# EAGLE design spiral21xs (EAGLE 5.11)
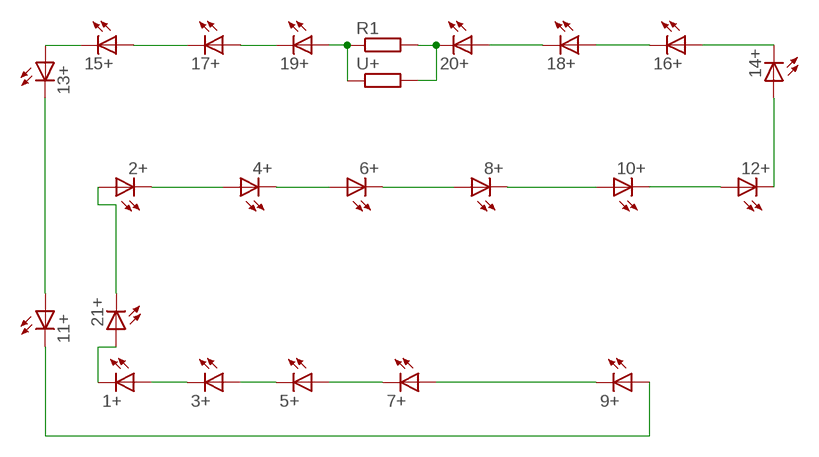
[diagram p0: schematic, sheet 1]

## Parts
1+  LEDSMD1210  [1210]
2+  LEDSMD1210  [1210]
3+  LEDSMD1210  [1210]
4+  LEDSMD1210  [1210]
5+  LEDSMD1210  [1210]
6+  LEDSMD1210  [1210]
7+  LEDSMD1210  [1210]
8+  LEDSMD1210  [1210]
9+  LEDSMD1210  [1210]
10+  LEDSMD1210  [1210]
11+  LEDSMD1210  [1210]
12+  LEDSMD1210  [1210]
13+  LEDSMD1210  [1210]
14+  LEDSMD1210  [1210]
15+  LEDSMD1210  [1210]
16+  LEDSMD1210  [1210]
17+  LEDSMD1210  [1210]
18+  LEDSMD1210  [1210]
19+  LEDSMD1210  [1210]
20+  LEDSMD1210  [1210]
21+  LEDSMD1210  [1210]
R1  R-EU_R1206  [R1206]
U+  R-EU_0204/2V  [0204V]

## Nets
MINUS: 20+.C R1.2 U+.2
N1-3: 1+.A 3+.C
N2-4: 2+.C 4+.A
N2-21: 2+.A 21+.C
N3-5: 3+.A 5+.C
N4-6: 4+.C 6+.A
N5-7: 5+.A 7+.C
N6-8: 6+.C 8+.A
N7-9: 7+.A 9+.C
N8-10: 8+.C 10+.A
N9-11: 9+.A 11+.C
N10-12: 10+.C 12+.A
N11-13: 11+.A 13+.C
N12-14: 12+.C 14+.A
N13-15: 13+.A 15+.C
N14-16: 14+.C 16+.A
N15-17: 15+.A 17+.C
N16-18: 16+.C 18+.A
N17-19: 17+.A 19+.C
N18-20: 18+.C 20+.A
N21-1: 1+.C 21+.A
PLUS: 19+.A R1.1 U+.1

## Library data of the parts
1+ 2+ 3+ 4+ 5+ 6+ 7+ 8+ 9+ 10+ 11+ 12+ 13+ 14+ 15+ 16+ 17+ 18+ 19+ 20+ 21+ = led(2):LED: LED
R1 U+ = rcl-2:R-EU_: RESISTOR, European symbol

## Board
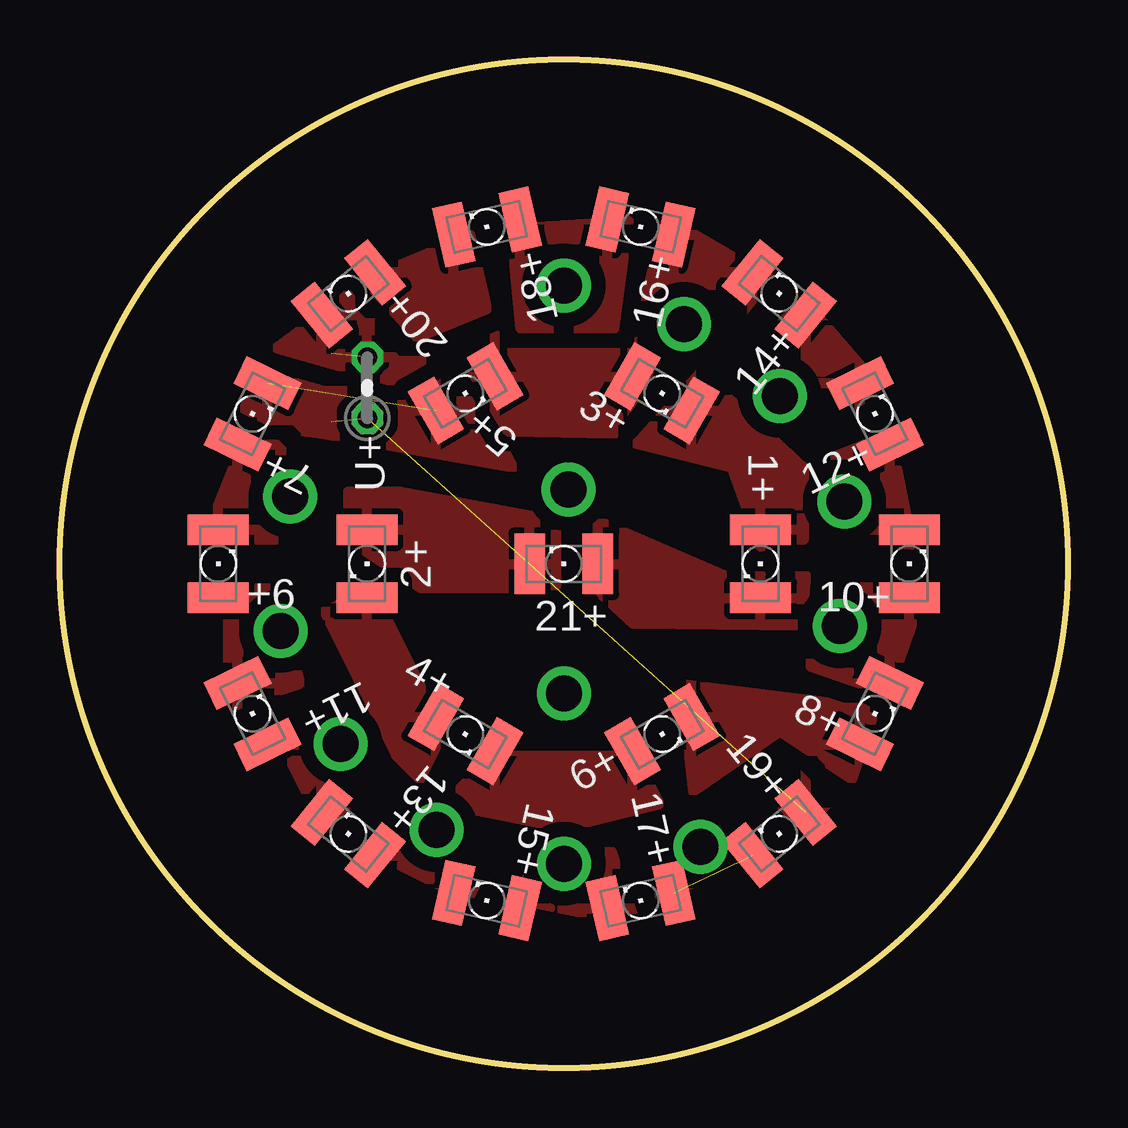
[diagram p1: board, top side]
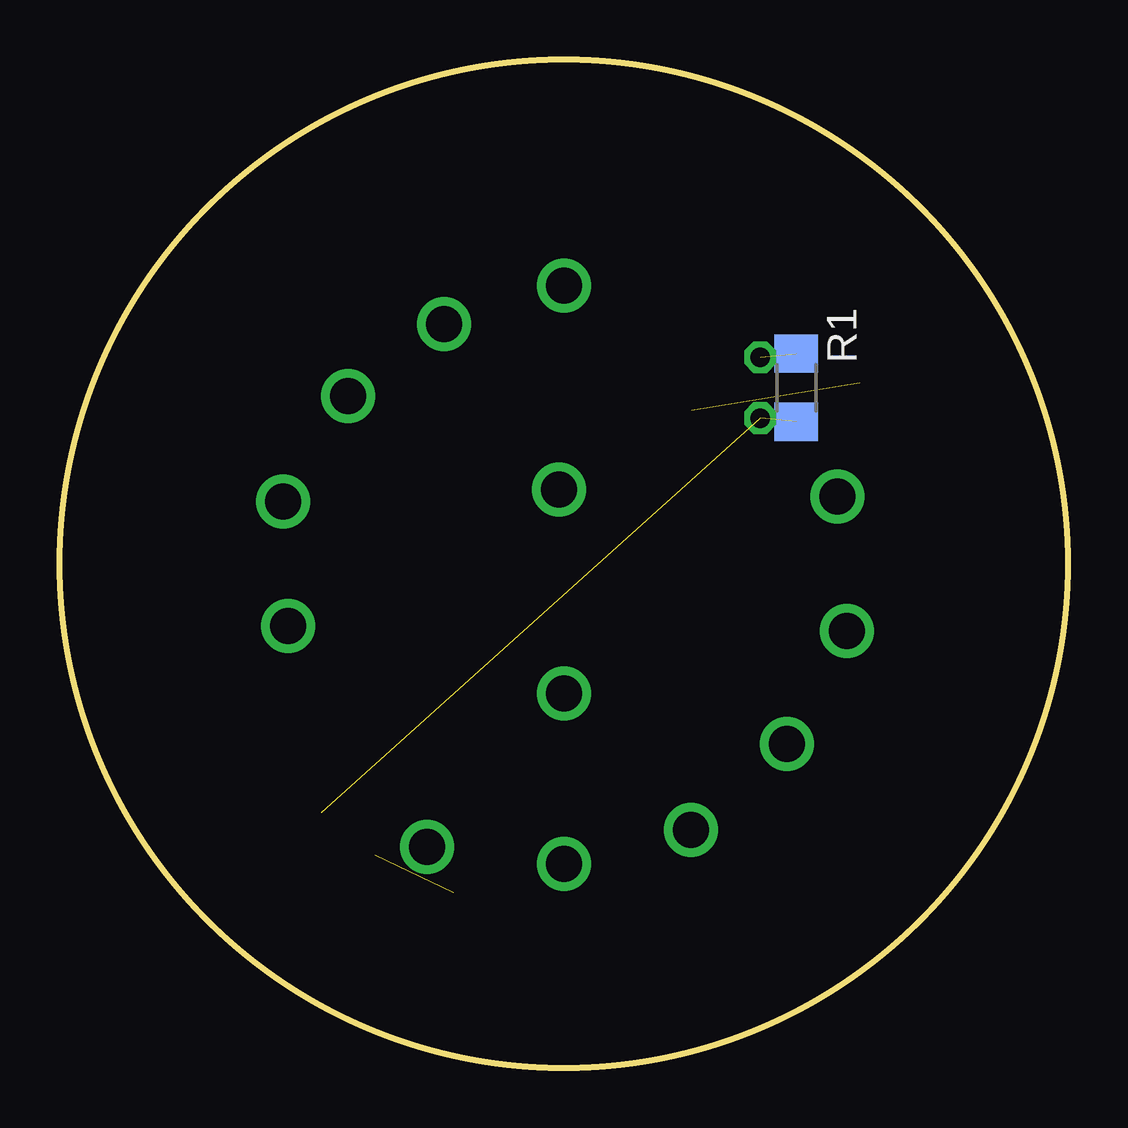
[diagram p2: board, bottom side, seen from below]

Size 42 x 42 mm. Coordinates in mm from the lower left corner, seen from the top.
Outline: circle at 21,21 radius 21
Copper layers (1*16): Top 0.035mm / dielectric 1.5mm / Bottom 0.035mm
Design rules "default": minimum track width 10mil, minimum drill 24mil, track to track 8mil, track to pad 8mil, pad to pad 8mil, via to via 8mil, smd to smd 8mil, copper to edge 40mil, drill to drill 8mil, minimum pad ring 10mil, minimum via ring 8mil, stop-mask expansion 4mil, vias tented up to drill 0mil, thermal gap 10mil

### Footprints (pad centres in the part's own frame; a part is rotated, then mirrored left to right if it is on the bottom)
1210 = smd 1.27 x 2.54: A -1.422,0; C 1.422,0
R1206 = smd 1.6 x 1.803: 1 -1.422,0; 2 1.422,0
0204V = drill 0.813 octagon: 1 -1.27,0; 2 1.27,0

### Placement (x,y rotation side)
1+  29.2,21 270 top
2+  12.8,21 270 top
3+  25.1,28.1 330 top
4+  16.9,13.9 330 top
5+  16.9,28.1 30 top
6+  25.1,13.9 30 top
7+  8.03,27.25 64 top
8+  33.97,14.75 64 top
9+  6.6,21 90 top
10+  35.4,21 90 top
11+  8.03,14.75 116 top
12+  33.97,27.25 116 top
13+  12.02,9.74 141 top
14+  29.98,32.26 141 top
15+  17.8,6.96 167 top
16+  24.2,35.04 167 top
17+  24.2,6.96 193 top
18+  17.8,35.04 193 top
19+  29.98,9.74 219 top
20+  12.02,32.26 219 top
21+  21,21 180 top
R1  11.31,28.34 90 bottom
U+  12.81,28.34 90 top

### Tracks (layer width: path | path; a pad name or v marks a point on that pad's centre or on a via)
HOL1  (via drill 1.5)
  other vias: 21,15.6
MINUS  (1 unrouted)
  pour Top (isolate 0.61, rank 3): 9,30 16,28 13,33
N1-3
  pour Top (isolate 0.61): 24,26 26.7,29 31,25 31,22 29.2,21.7 28,25
N2-4
  pour Top (isolate 0.61, rank 2): 13,20 11,19 14,13 15,12 16,14
N2-21
  pour Top (isolate 0.61, rank 2): 12,24 12,22 15,20 20,20 20.7,20.1 20.7,22.8 14.2,24
N3-5
  pour Top (isolate 0.61, rank 3): 17.2,29 17.2,30.7 25.2,30.2 23.1,26.4 18.7,26.5
N4-6
  pour Top (isolate 0.61, rank 2): 18,13 17,12 16,11 21,10 25,11 24,13 20,13
N5-7  (1 unrouted)
  pour Top (isolate 0.61, rank 4): 8,29 16.8,28.9 18.9,25 10.9,26.4 7.6,26.8
N6-8
  pour Top (isolate 0.61, rank 3): 26,15 26,16 34,15 33,12 30,14 26.4,11.5
N7-9
  pour Top (isolate 0.61, rank 2): 8,27 10,25 9,22 6,22
N8-10
  pour Top (isolate 0.61, rank 2): 31,20 36.1,20.1 34.5,15.6 31.3,16.7
N9-11
  pour Top (isolate 0.61, rank 2): 7,20 9,20 10,16 7,15
N10-12
  pour Top (isolate 0.61, rank 2): 31,25 34.6,26.4 35.5,21.8 31.1,21.7
N11-13
  pour Top (isolate 0.61, rank 2): 9,14 11,15 13,12 11,10
N12-14
  pour Top (isolate 0.61, rank 2): 31,32 34.2,28.3 31.2,26.5 28.3,29.3
N13-15
  pour Top (isolate 0.61, rank 2): 13,9 14,11 18,9 17,7
N14-16
  pour Top (isolate 0.61, rank 2): 26,35 29.6,32.9 27.4,30.2 24.3,31.6 25.2,35.2
N15-17
  pour Top (isolate 0.61, rank 2): 19,7 20,9 23,9 24,6
N16-18
  pour Top (isolate 0.61, rank 2): 19,35 23.7,35.3 23.1,30.8 19.2,30.8 18.8,35
N17-19  (1 unrouted)
  pour Top (isolate 0.61, rank 2): 25,7 25,9 28,10 29,9
N18-20
  pour Top (isolate 0.61, rank 2): 13,33 17.1,34.7 17.8,31.6 14.9,30.4 12.9,32.6
N21-1
  pour Top (isolate 0.61): 22,22 22,23 27.8,20.5 31.1,20.5 30.9,18.4 23.9,18.5 22.6,19.7
N$1  (via drill 1.5)
  other vias: 26,31
N$2  (via drill 1.5)
  other vias: 30,28
N$3  (via drill 1.5)
  other vias: 32.7,23.6
N$4  (via drill 1.5)
  other vias: 32.5,18.4
N$5  (via drill 1.5)
  other vias: 26.7,9.2
N$6  (via drill 1.5)
  other vias: 21,8.5
N$7  (via drill 1.5)
  other vias: 15.7,9.9
N$8  (via drill 1.5)
  other vias: 11.7,13.5
N$9  (via drill 1.5)
  other vias: 9.2,18.2
N$10  (via drill 1.5)
  other vias: 9.6,23.8
N$11  (via drill 1.5)
  other vias: 21,32.6
N$12  (via drill 1.5)
  other vias: 21.2,24.1
PLUS  (2 unrouted)
  pour Top (isolate 0.61, rank 2): 29,12 30,13 32,11 31,10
